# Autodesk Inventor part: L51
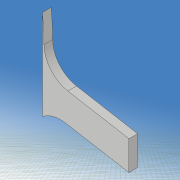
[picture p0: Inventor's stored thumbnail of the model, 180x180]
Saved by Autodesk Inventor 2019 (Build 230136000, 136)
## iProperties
Created: 2021-05
Part Number: L51
Material: 一般
Document SubType Name: Modeling
Designer: kikut
Density: 1 g/cm^3
Appearance: 既定
Mass: 0.00934248 g
Surface Area: 0.426451 cm^2
Volume: 0.00934248 cm^3
Author: kikut
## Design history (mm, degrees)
sketch "スケッチ1"
  geometry: L1 (80, 60)-(-80, 60); L2 (-80, 60)-(-80, -60); L3 (-80, -60)-(80, -60); L4 (80, -60)-(80, 60); L5 (80, 60)-(-80, -60); L6 (-80, 60)-(80, -60); 1 further point
  constraints: 12 end point, 2 midpoint, 2 parallel, 1 horizontal, 1 perpendicular
  dimensions: "d0" = 160 distance of L2.end L3.end; "d1" = 120 distance of L1.end L2.end
extrude "押し出し1" new body sketch "スケッチ1" stored distance "d2" = 0.6; taper "d3" = 0 deg
sketch "スケッチ2"
  geometry: L1 (-140, 0)-(140, 0) reference; L2 (0, -54)-(20, -30); L3 (0, 54)-(20, 30); L4 (0, -3)-(6.514, -3); L5 (6.514, -3)-(16, -6); L6 (16, -6)-(24, -3); L7 (24, -3)-(33.716, -3); L8 (0, 3)-(6.514, 3); L9 (6.514, 3)-(16, 6); L10 (16, 6)-(24, 3); L11 (24, 3)-(33.716, 3); L12 (0, -98)-(0, 98) reference; L13 (-100, -70)-(100, -70); L14 (100, -70)-(100, 70); L15 (100, 70)-(-100, 70); L16 (-100, 70)-(-100, -70); L17 (-100, -70)-(100, 70); L18 (100, -70)-(-100, 70); A1 r 60 centre (54.312, 28.5) between (0, 54) and (0, 3); A2 r 60 centre (54.312, -28.5) between (0, -3) and (0, -54); A3 r 18.111 centre (18, -12) between (20, -30) and (33.716, -3); A4 r 18.111 centre (18, 12) between (33.716, 3) and (20, 30); 1 further point
  constraints: 32 end point, 8 point on circle, 8 symmetric about line, 4 centre point, 3 horizontal, 2 collinear, 2 midpoint, 2 parallel, 1 perpendicular
  dimensions: "d5" = 60 radius of A1; "d6" = 6 distance of L8.start L4.start; "d7" = 108 distance of L3.start L2.start; "d8" = 0 horizontal distance of L3.start L8.start; "d9" = 60 distance of L3.end L2.end; "d10" = 0 horizontal distance of point (0, 0) L3.start; "d11" = 20 horizontal distance of L3.start L3.end; "d12" = 24 distance of A4.centre A3.centre; "d13" = 6 distance of L11.end L7.end; "d14" = 12 distance of L9.end L5.end; "d15" = 16 distance from line of L12 L5.end; "d16" = 24 distance from line of L6.end L12; "d17" = 200 distance of L14.end L15.end; "d18" = 140 distance of L15.end L13.start; "d30" = 18 distance from line of L12 A4.centre
extrude "押し出し2" cut sketch "スケッチ2" stored distance "d19" = 10; taper "d20" = 0 deg
sketch "スケッチ3"
  geometry: L1 (49.705, -17.97)-(33.948, -15.191); L2 (33.948, -15.191)-(34.295, -13.222); L3 (34.295, -13.222)-(50.052, -16); L4 (50.052, -16)-(49.705, -17.97); L5 (49.705, -17.97)-(34.295, -13.222); L6 (33.948, -15.191)-(50.052, -16); L7 (50.052, 16)-(34.295, 13.222); L8 (34.295, 13.222)-(33.948, 15.191); L9 (33.948, 15.191)-(49.705, 17.97); L10 (49.705, 17.97)-(50.052, 16); L11 (50.052, 16)-(33.948, 15.191); L12 (34.295, 13.222)-(49.705, 17.97); L13 (-112, 0)-(112, 0) reference; L14 (0, -84)-(0, 84) reference; 3 further points
  constraints: 24 end point, 4 midpoint, 4 parallel, 2 perpendicular, 2 symmetric about line
  dimensions: "d21" = 2 distance of L3.end L1.start; "d22" = 2 distance of L9.end L7.start; "d23" = 16 distance of L8.end L9.end; "d24" = 42 distance from line of L14 point (42, 15.596); "d26" = 10 deg angle of L7 L13; "d62" = 16 distance from line of L3.end L13
extrude "押し出し3" join sketch "スケッチ3" distance "d27" = 0.6; taper "d28" = 0 deg
fillet "フィレット1" dims "d31" = 2
fillet "フィレット2" dims "d32" = 1
sketch "スケッチ7"
  geometry: L1 (-20, 60)-(80, 60); L2 (80, 60)-(80, -60); L3 (80, -60)-(-20, -60); L4 (-20, -60)-(-20, 60); L5 (0, -82.207)-(0, 85.793) reference; L6 (-40, 0)-(100, 0) reference; L7 (36, -10)-(42, -10); L8 (42, -10)-(42, -20); L9 (42, -20)-(36, -20); L10 (36, -20)-(36, -10); 1 further point
  constraints: 16 end point, 4 parallel, 2 horizontal, 2 perpendicular, 1 other
  dimensions: "d80" = 120 distance of L3.end L1.start; "d81" = 20 distance between parallel lines of L5 L4; "d82" = 100 distance of L1.start L1.end; "d84" = 6 distance of L8.end L9.end; "d85" = 10 distance of L7.end L8.end; "d86" = 56 distance between parallel lines of L4 L10; "d93" = 40 distance between parallel lines of L3 L9
extrude "押し出し5" cut sketch "スケッチ7" stored distance "d87" = 10; taper "d88" = 0 deg
node "ソリッド1"
